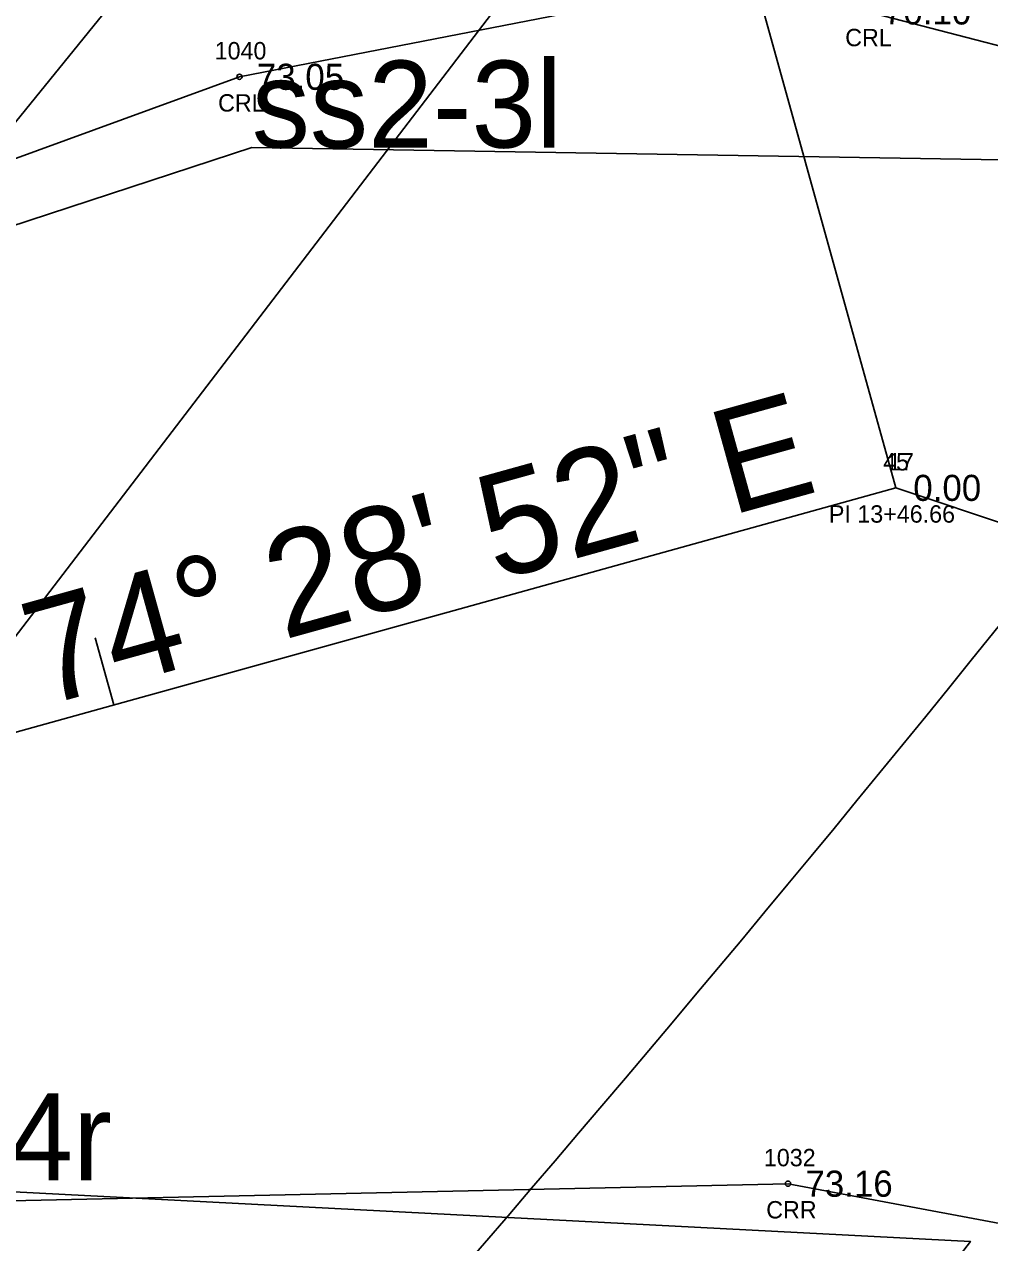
# Model space of a CAD drawing. Extents: x 2500794 to 2511032, y 910653 to 917533.
# Drawn here: x 2505897.8 to 2505953.3, y 913471.7 to 913541.8 of the extents above; entities that cross this region are included whole.
import ezdxf

# ---------------------------------------------------------------- set-up
doc = ezdxf.new("R2010")
doc.units = 0
for name, color, linetype in [('Default', 7, 'Continuous'), ('RD_EX_H2O', 7, 'Continuous'), ('RD_EX_H2O_txCode', 7, 'Continuous'), ('RD_EX_H2O_WetLd', 7, 'Continuous'), ('RD_EX_RW', 7, 'Continuous'), ('RD_EX_TX_H2O_ELEV', 7, 'Continuous'), ('RD_HC_Cl', 7, 'Continuous'), ('RD_HC_Data', 7, 'Continuous'), ('RD_HC_Data_Tic', 7, 'Continuous'), ('RD_HC_Survey_ELEV', 7, 'Continuous'), ('RD_HC_txCode', 7, 'Continuous'), ('RD_Sketch9', 7, 'Continuous'), ('RD_SMD_Locator', 7, 'Continuous'), ('RD_XS_NPDES', 7, 'Continuous')]:
    doc.layers.add(name, color=color, linetype=linetype)

# ---------------------------------------------------------------- blocks, each defined once
blk = doc.blocks.new('POINT_DISPLAY')
at = {"layer": 'Default'}
blk.add_line((0, 0), (0, 0), dxfattribs=at)
blk = doc.blocks.new('Non-Wetland Waters (Tributaries)')
at = {"layer": 'Default'}
for points in [[(636523.855, 232037.448), (636501.371, 232037.816), (636484.456, 232032.271), (636479.967, 232030.855)], [(636470.177, 232019.736), (636472.749, 232019.524), (636488.229, 232016.145), (636494.608, 232022.734), (636511.865, 232021.84)]]:
    blk.add_lwpolyline(points, dxfattribs=at)
blk = doc.blocks.new('Wetlands')
at = {"layer": 'Default'}
for points in [[(636578.378, 232108.026), (636523.855, 232037.448), (636501.371, 232037.816), (636484.456, 232032.271), (636499.849, 232049.322), (636504.147, 232059.556), (636518.345, 232075.791), (636532.382, 232092.673), (636539.146, 232087.393), (636544.708, 232099.914), (636554.736, 232107.733), (636570.529, 232108.061), (636578.378, 232108.026)], [(636454.761, 231993.951), (636472.749, 232019.524), (636488.229, 232016.145), (636494.608, 232022.734), (636511.865, 232021.84), (636504.627, 232012.418), (636482.687, 231983.857)]]:
    blk.add_lwpolyline(points, dxfattribs=at)

msp = doc.modelspace()

# ---------------------------------------------------------------- linework, layer by layer
at = {"layer": 'RD_EX_H2O_txCode'}
for points in [[(2505762.262, 913658.109), (2505746.145, 913644.246), (2505726.467, 913615.205), (2505674.206, 913628.007), (2505666.247, 913620.583), (2505714.598, 913592.147), (2505793.902, 913560.447), (2505801.323, 913552.799), (2505803.704, 913539.769), (2505832.625, 913516.964), (2505848.424, 913517.193), (2505881.862, 913528.443), (2505910.198, 913538.779), (2505939.304, 913544.448), (2505946.254, 913542.537), (2505974.653, 913535.178), (2506004.111, 913524.704), (2506052.031, 913515.471), (2506115.491, 913494.68), (2506138.045, 913548.886)], [(2505789.475, 913464.314), (2505795.694, 913463.103), (2505812.13, 913464.368), (2505832.031, 913446.726), (2505876.169, 913453.079), (2505891.756, 913474.027), (2505941.737, 913475.129), (2505995.42, 913465.054), (2506040.13, 913447.397), (2506076.302, 913432.472), (2506096.958, 913385.48)]]:
    msp.add_lwpolyline(points, dxfattribs=at)
at = {"layer": 'RD_EX_RW'}
msp.add_line((2505867.15, 913467.138), (2505934.138, 913554.757), dxfattribs=at)
at = {"layer": 'RD_HC_Cl'}
for p, q in [((2505891.844, 913499.564), (2505947.94, 913515.141)), ((2505947.94, 913515.141), (2506096.51, 913465.315))]:
    msp.add_line(p, q, dxfattribs=at)
at = {"layer": 'RD_HC_Data'}
msp.add_line((2505947.94, 913515.141), (2505916.851, 913627.099), dxfattribs=at)
at = {"layer": 'RD_HC_Data_Tic'}
msp.add_line((2505902.98, 913502.656), (2505901.91, 913506.511), dxfattribs=at)
at = {"layer": 'RD_Sketch9'}
msp.add_arc((2504883.086, 914369.786), 1375, 311.510647, 322.600707, dxfattribs=at)
at = {"layer": 'RD_SMD_Locator'}
for centre in [(2505910.198, 913538.779), (2505941.737, 913475.129)]:
    msp.add_circle(centre, 0.15, dxfattribs=at)
at = {"layer": 'RD_XS_NPDES'}
msp.add_line((2505884.036, 913519.799), (2505907.872, 913549.195), dxfattribs=at)

# ---------------------------------------------------------------- block references
at = {"layer": 'Default', "xscale": 3.937007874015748, "yscale": 3.937007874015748}
for name, p in [('Wetlands', (0, 0)), ('Non-Wetland Waters (Tributaries)', (0, 0)), ('POINT_DISPLAY', (2505910.908, 913534.707)), ('POINT_DISPLAY', (2505910.908, 913534.707))]:
    msp.add_blockref(name, p, dxfattribs=at)
at = {"layer": 'RD_EX_H2O', "xscale": 3.937007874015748, "yscale": 3.937007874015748}
msp.add_blockref('Non-Wetland Waters (Tributaries)', (0, 0), dxfattribs=at)
at = {"layer": 'RD_EX_H2O_WetLd', "xscale": 3.937007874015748, "yscale": 3.937007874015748}
msp.add_blockref('Wetlands', (0, 0), dxfattribs=at)

# ---------------------------------------------------------------- texts
at = {"layer": 'Default'}
for s, p in [('ss2-3l', (2505910.908, 913534.707)), ('ss2-3l', (2505910.908, 913534.707)), ('ss2-4r', (2505884.283, 913475.33)), ('ss2-4r', (2505884.283, 913475.33))]:
    msp.add_text(s, height=5, dxfattribs=at).set_placement(p)
at = {"layer": 'RD_EX_H2O_txCode'}
for s, p in [('CRL', (2505945.026, 913540.537)), ('1040', (2505908.773, 913539.779)), ('CRL', (2505908.97, 913536.779)), ('1032', (2505940.351, 913476.129)), ('CRR', (2505940.485, 913473.129))]:
    msp.add_text(s, height=1, dxfattribs=at).set_placement(p)
at = {"layer": 'RD_EX_TX_H2O_ELEV'}
for s, p in [('70.10', (2505947.254, 913541.787)), ('73.05', (2505911.198, 913538.029)), ('73.16', (2505942.737, 913474.379))]:
    msp.add_text(s, height=1.5, dxfattribs=at).set_placement(p)
at = {"layer": 'RD_HC_Data'}
msp.add_text('N 74%%d 28\' 52" E', height=6, rotation=15.51899, dxfattribs=at).set_placement((2505891.151, 913500.409))
at = {"layer": 'RD_HC_Survey_ELEV'}
msp.add_text('0.00', height=1.5, dxfattribs=at).set_placement((2505948.94, 913514.391))
msp.add_text('0.00', height=1.5, dxfattribs=at).set_placement((2505948.94, 913514.391))
at = {"layer": 'RD_HC_txCode'}
for s, p in [('45', (2505947.207, 913516.141)), ('17', (2505947.491, 913516.141)), ('PI 13+46.66', (2505944.089, 913513.141)), ('PI 13+46.66', (2505944.089, 913513.141))]:
    msp.add_text(s, height=1, dxfattribs=at).set_placement(p)

doc.saveas('drawing.dxf')
